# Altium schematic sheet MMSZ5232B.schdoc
size 127 x 101 mm
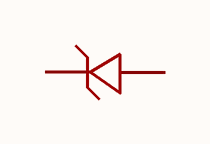
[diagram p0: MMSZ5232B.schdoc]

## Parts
ZD?  mmsz5232b_c21554  [SOD-123_L2.8-W1.8-LS3.7-RD]  (value not drawn)

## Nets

Not connected (* = marked no-connect by the designer): ZD? 1(K) 2(A)

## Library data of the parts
ZD? = mmsz5232b_c21554: 二极管配置:1个独立式;稳压值(标称值):5.6V;稳压值(范围):5.32V~5.88V;耗散功率(Pd):350mW;; Manufacturer: CJ(江苏长电/长晶); AddInBom: yes; ModelId: 7884390a25fb4c08947731ebfba7e3f8; ModelTransform: 144.8816,62.992,0,0,0,0,0,0,0; Diode Configuration: 1个独立式; Zener Voltage(Nom): 5.6V; Reverse Leakage Current (Ir): 5uA@3V; Pd - Power Dissipation: 350mW; Impedance(Zzt): 11Ω; Impedance(Zzk): 1.6kΩ; Operating Junction Temperature Range: -65℃~+150℃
